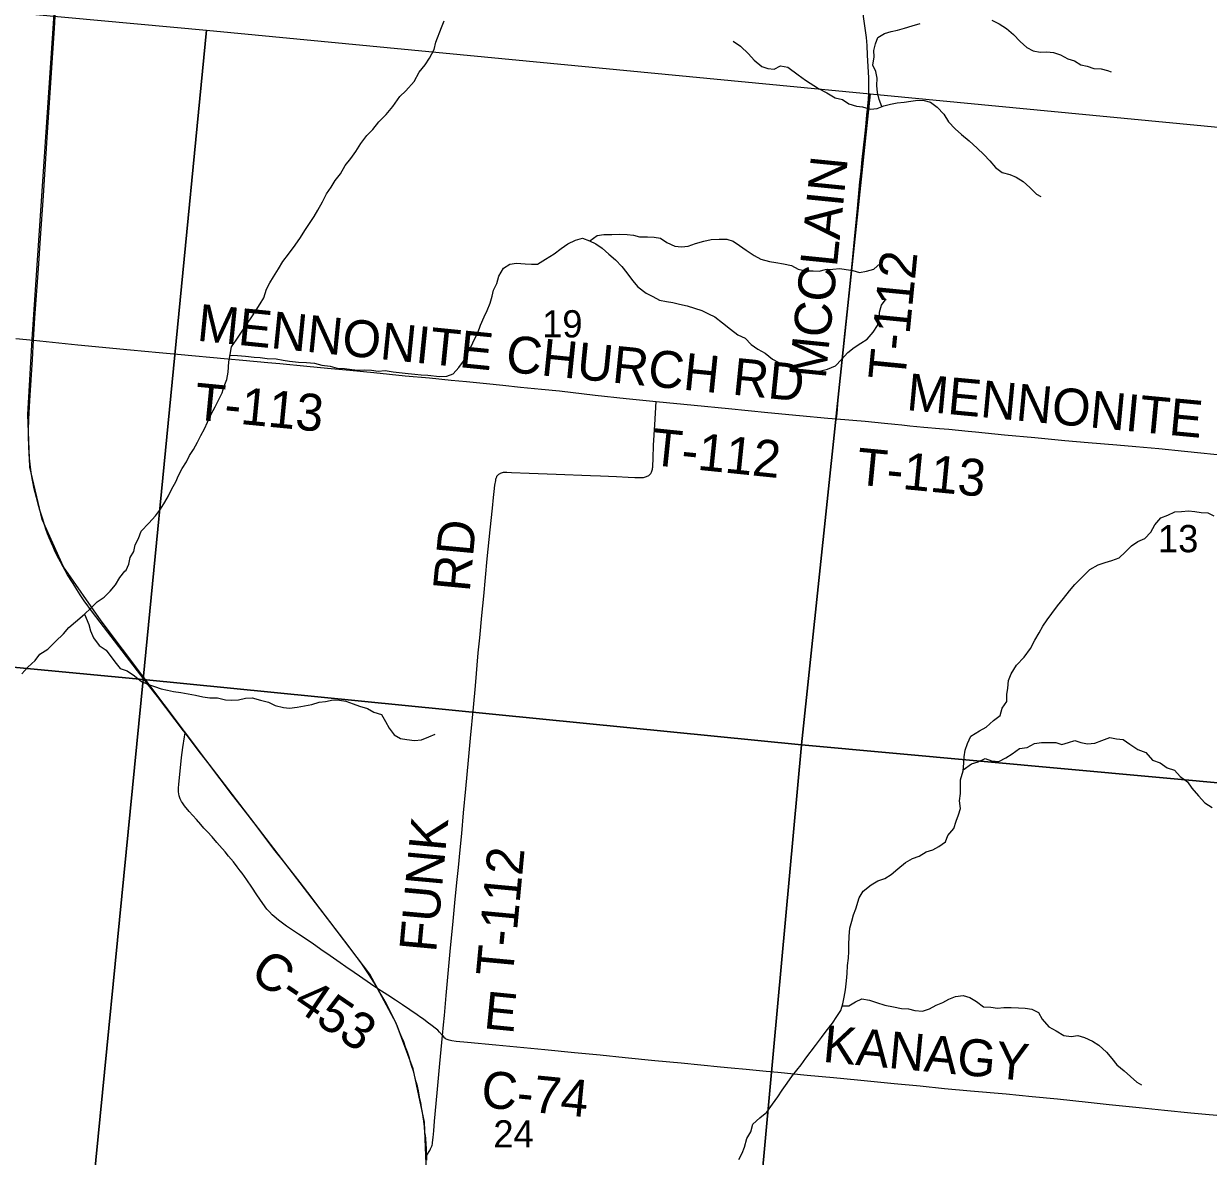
# Model space of a CAD drawing. Extents: x 831 to 1552, y 430 to 870.
# Drawn here: x 993.28 to 1029.71, y 742.52 to 777.36 of the extents above; entities that cross this region are included whole.
import ezdxf

# ---------------------------------------------------------------- set-up
doc = ezdxf.new("R2010")
doc.units = 0
for name, color, linetype in [('GM_X_Corporation', 7, 'Continuous'), ('GM_X_County_Road', 7, 'Continuous'), ('GM_X_County_Road_Text', 7, 'Continuous'), ('GM_X_Minor_River', 7, 'Continuous'), ('GM_X_Rail_Line', 7, 'Continuous'), ('GM_X_Section_Text', 7, 'Continuous'), ('GM_X_Township_Road', 7, 'Continuous'), ('GM_X_Township_Road_Text', 7, 'Continuous'), ('GM_X_US_Route', 7, 'Continuous')]:
    doc.layers.add(name, color=color, linetype=linetype)

msp = doc.modelspace()

# ---------------------------------------------------------------- linework, layer by layer
at = {"layer": 'GM_X_Corporation'}
for points in [[(998.895, 777.157), (996.953, 757.185), (977.893, 758.996), (979.447, 778.955)], [(1019.314, 775.201), (1017.196, 755.179), (996.953, 757.185), (998.895, 777.157)], [(1019.314, 775.201), (1040.822, 773.14), (1038.88, 753.198), (1017.196, 755.179)], [(996.953, 757.185), (994.975, 737.085), (974.695, 738.984), (977.893, 758.996)], [(1017.196, 755.179), (1015.357, 735.031), (994.975, 737.085), (996.953, 757.185)], [(1017.196, 755.179), (1038.88, 753.198), (1036.878, 732.803), (1015.357, 735.031)]]:
    msp.add_lwpolyline(points, close=True, dxfattribs=at)
at = {"layer": 'GM_X_County_Road'}
for points in [[(993.037, 767.675), (993.579, 767.622)], [(1004.165, 747.671), (1003.939, 747.827), (1003.602, 748.061), (1003.44, 748.175), (1003.185, 748.353), (1003.011, 748.473), (1002.706, 748.687), (1002.419, 748.884), (1002.144, 749.076), (1001.73, 749.351), (1001.361, 749.604), (1001.239, 749.69), (1001.109, 749.788), (1000.984, 749.892), (1000.919, 749.951), (1000.832, 750.041), (1000.758, 750.126), (1000.631, 750.296), (1000.446, 750.562), (1000.289, 750.801), (1000.135, 751.026), (999.993, 751.227), (999.937, 751.305), (999.847, 751.422), (999.725, 751.576), (999.576, 751.757), (999.474, 751.881), (999.3, 752.085), (999.219, 752.177), (999.071, 752.343), (998.93, 752.5), (998.821, 752.618), (998.722, 752.73), (998.59, 752.879), (998.366, 753.129), (998.222, 753.298), (998.199, 753.328), (998.156, 753.392), (998.132, 753.434), (998.108, 753.476), (998.093, 753.516), (998.079, 753.55), (998.063, 753.605), (998.05, 753.665), (998.041, 753.729), (998.038, 753.786), (998.039, 753.843), (998.046, 753.967), (998.074, 754.265), (998.134, 754.784), (998.172, 755.092), (998.223, 755.426), (998.241, 755.543)], [(1006.154, 746.232), (1006.062, 746.339), (1006.01, 746.395), (1005.934, 746.463), (1005.841, 746.537), (1005.69, 746.65), (1005.572, 746.736), (1005.492, 746.794), (1005.379, 746.871), (1004.932, 747.184), (1004.714, 747.328), (1004.472, 747.477), (1004.165, 747.671)], [(1005.671, 742.55), (1005.764, 742.701), (1005.791, 742.745), (1005.813, 742.786), (1005.83, 742.829), (1005.84, 742.867), (1005.847, 742.9), (1005.853, 742.946), (1005.869, 743.099), (1005.889, 743.306), (1005.915, 743.598), (1005.994, 744.47), (1006.079, 745.379), (1006.154, 746.232)], [(1006.154, 746.232), (1006.198, 746.187), (1006.239, 746.153), (1006.263, 746.138), (1006.292, 746.123), (1006.325, 746.111), (1006.356, 746.102), (1006.399, 746.093), (1006.443, 746.085), (1006.579, 746.066), (1006.926, 746.034), (1007.801, 745.952), (1009.302, 745.808), (1010.214, 745.715), (1011.009, 745.643), (1011.775, 745.563), (1012.69, 745.471), (1013.494, 745.391), (1014.707, 745.273), (1015.041, 745.24), (1015.498, 745.196), (1016.116, 745.141), (1016.475, 745.106), (1017.378, 745.019), (1018.182, 744.942), (1018.923, 744.87), (1020.055, 744.762), (1020.851, 744.683), (1021.602, 744.609), (1022.403, 744.538), (1023.491, 744.44), (1024.29, 744.364), (1025.076, 744.285), (1026.02, 744.186), (1026.664, 744.117), (1027.582, 744.025), (1028.364, 743.943), (1029.176, 743.858), (1030.422, 743.742)]]:
    msp.add_lwpolyline(points, dxfattribs=at)
at = {"layer": 'GM_X_Minor_River'}
for points in [[(996.427, 760.548), (996.514, 760.738), (996.554, 760.936), (996.663, 761.126), (996.702, 761.331), (996.803, 761.521), (996.889, 761.749), (997.12, 761.998), (997.335, 762.225), (997.481, 762.429), (997.62, 762.641), (997.729, 762.838), (997.829, 763.051), (997.953, 763.271), (998.039, 763.461), (998.155, 763.681), (998.286, 763.885), (998.379, 764.075), (998.503, 764.265), (998.627, 764.484), (998.72, 764.689), (998.836, 764.902), (998.929, 765.099), (999.045, 765.35), (999.169, 765.577), (999.263, 765.782), (999.379, 766.002), (999.442, 766.215), (999.527, 766.42), (999.567, 766.641), (999.585, 766.961), (999.625, 767.182), (999.665, 767.425), (999.812, 767.63), (999.974, 767.872), (1000.113, 768.077), (1000.275, 768.312), (1000.422, 768.547), (1000.545, 768.744), (1000.661, 768.933), (1000.74, 769.192), (1000.848, 769.389), (1000.964, 769.578), (1001.111, 769.821), (1001.25, 770.048), (1001.419, 770.276), (1001.627, 770.548), (1001.789, 770.783), (1001.921, 770.995), (1002.067, 771.215), (1002.206, 771.427), (1002.322, 771.624), (1002.469, 771.882), (1002.593, 772.125), (1002.732, 772.33), (1002.856, 772.534), (1003.018, 772.746), (1003.165, 772.997), (1003.334, 773.216), (1003.488, 773.428), (1003.65, 773.678), (1003.828, 773.921), (1004.02, 774.11), (1004.204, 774.344), (1004.427, 774.571), (1004.627, 774.813), (1004.843, 775.124), (1005.035, 775.297), (1005.282, 775.585), (1005.436, 775.865), (1005.621, 776.093), (1005.76, 776.297), (1005.9, 776.57), (1005.955, 776.791), (1006.126, 777.239), (1006.212, 777.452)], [(1019.667, 774.809), (1019.585, 775.034), (1019.541, 775.24), (1019.52, 775.461), (1019.53, 775.682), (1019.486, 775.889), (1019.396, 776.088), (1019.436, 776.339), (1019.423, 776.537), (1019.478, 776.743), (1019.548, 776.933), (1019.755, 777.06), (1019.954, 777.119), (1020.152, 777.163), (1020.373, 777.222), (1020.602, 777.296), (1020.847, 777.371)], [(1023.056, 777.465), (1023.276, 777.356), (1023.503, 777.209), (1023.722, 777.024), (1023.926, 776.816), (1024.13, 776.631), (1024.327, 776.523), (1024.54, 776.49), (1024.745, 776.496), (1024.951, 776.471), (1025.171, 776.401), (1025.391, 776.284), (1025.596, 776.214), (1025.793, 776.098), (1025.983, 776.058), (1026.195, 775.987), (1026.416, 775.97), (1026.613, 775.922), (1026.72, 775.883)], [(1015.1, 776.821), (1015.32, 776.674), (1015.569, 776.435), (1015.742, 776.236), (1015.977, 776.043), (1016.167, 775.98), (1016.364, 775.963), (1016.556, 776.06), (1016.784, 776.02), (1017.094, 775.789), (1017.328, 775.619), (1017.722, 775.371), (1017.98, 775.231), (1018.237, 775.077), (1018.458, 775.029), (1018.655, 774.897), (1018.89, 774.819), (1019.08, 774.802), (1019.323, 774.731), (1019.529, 774.752), (1019.728, 774.834), (1019.934, 774.886), (1020.14, 774.922), (1020.361, 774.943), (1020.559, 774.979), (1020.78, 775.008), (1020.97, 774.998), (1021.168, 774.951), (1021.372, 774.796), (1021.576, 774.581), (1021.726, 774.343), (1021.93, 774.128), (1022.126, 773.951), (1022.36, 773.758), (1022.602, 773.535), (1022.806, 773.342), (1022.995, 773.142), (1023.168, 772.942), (1023.372, 772.788), (1023.608, 772.717), (1023.805, 772.639), (1024.017, 772.508), (1024.228, 772.323), (1024.432, 772.115), (1024.561, 772.045)], [(999.622, 767.162), (999.853, 767.149), (1000.097, 767.131), (1000.363, 767.106), (1000.553, 767.089), (1000.766, 767.064), (1001.04, 767.047), (1001.261, 767.014), (1001.451, 766.982), (1001.725, 766.949), (1001.976, 766.939), (1002.22, 766.914), (1002.447, 766.858), (1002.706, 766.825), (1002.919, 766.762), (1003.139, 766.753), (1003.368, 766.72), (1003.558, 766.703), (1003.748, 766.709), (1003.969, 766.699), (1004.182, 766.667), (1004.395, 766.695), (1004.639, 766.655), (1004.913, 766.622), (1005.103, 766.605), (1005.308, 766.58), (1005.498, 766.563), (1005.704, 766.546), (1006.069, 766.505), (1006.29, 766.518), (1006.481, 766.585), (1006.665, 766.789), (1006.835, 767.024), (1006.913, 767.213), (1007.044, 767.433), (1007.145, 767.661), (1007.246, 767.851), (1007.324, 768.086), (1007.441, 768.345), (1007.534, 768.534), (1007.62, 768.762), (1007.682, 768.975), (1007.73, 769.165), (1007.831, 769.37), (1007.894, 769.598), (1008.033, 769.841), (1008.232, 769.961), (1008.438, 769.997), (1008.696, 769.972), (1008.894, 769.963), (1009.085, 769.961), (1009.33, 770.119), (1009.59, 770.284), (1009.805, 770.442), (1010.012, 770.593), (1010.249, 770.697), (1010.462, 770.764), (1010.683, 770.678), (1010.872, 770.593), (1011.069, 770.454), (1011.273, 770.276), (1011.477, 770.099), (1011.673, 769.891), (1011.831, 769.692), (1011.997, 769.462), (1012.17, 769.262), (1012.427, 769.069), (1012.632, 768.968), (1012.837, 768.859), (1013.049, 768.811), (1013.247, 768.787), (1013.452, 768.731), (1013.688, 768.684), (1013.908, 768.605), (1014.136, 768.542), (1014.34, 768.434), (1014.538, 768.34), (1014.772, 768.155), (1015.014, 767.962), (1015.241, 767.785), (1015.468, 767.684), (1015.649, 767.492), (1015.854, 767.345), (1016.081, 767.221), (1016.308, 767.043), (1016.505, 766.935), (1016.702, 766.849), (1016.937, 766.756), (1017.127, 766.693), (1017.386, 766.675), (1017.599, 766.658), (1017.79, 766.679), (1018.003, 766.731), (1018.248, 766.835), (1018.432, 767.032), (1018.625, 767.243), (1018.824, 767.402), (1019.023, 767.529), (1019.215, 767.657), (1019.407, 767.869), (1019.538, 768.081)], [(1010.685, 770.677), (1010.92, 770.844), (1011.118, 770.872), (1011.362, 770.878), (1011.591, 770.891), (1011.834, 770.881), (1012.032, 770.856), (1012.222, 770.809), (1012.466, 770.807), (1012.671, 770.797), (1012.861, 770.765), (1013.058, 770.633), (1013.301, 770.517), (1013.514, 770.492), (1013.712, 770.513), (1013.941, 770.595), (1014.201, 770.676), (1014.422, 770.72), (1014.666, 770.733), (1014.902, 770.731), (1015.099, 770.668), (1015.296, 770.537), (1015.5, 770.398), (1015.742, 770.228), (1015.947, 770.119), (1016.213, 770.048), (1016.411, 770.016), (1016.646, 769.975), (1016.889, 769.927), (1017.102, 769.811), (1017.322, 769.756), (1017.558, 769.761), (1017.748, 769.744), (1017.939, 769.796), (1018.168, 769.809), (1018.381, 769.83), (1018.579, 769.798), (1018.784, 769.773), (1018.982, 769.71), (1019.203, 769.746), (1019.424, 769.813), (1019.624, 769.986), (1019.616, 769.956)], [(1019.538, 768.081), (1019.586, 768.287), (1019.603, 768.485), (1019.658, 768.705), (1019.804, 768.902)], [(1018.652, 749.024), (1018.662, 749.283), (1018.687, 749.534), (1018.75, 749.755), (1018.797, 749.944), (1018.867, 750.134), (1018.97, 750.476), (1019.093, 750.68), (1019.346, 750.869), (1019.553, 750.989), (1019.767, 751.063), (1019.958, 751.191), (1020.165, 751.364), (1020.403, 751.56), (1020.61, 751.68), (1020.824, 751.754), (1021.038, 751.882), (1021.237, 751.948), (1021.428, 752.053), (1021.627, 752.196), (1021.705, 752.386), (1021.882, 752.605), (1021.953, 752.826), (1022.031, 753.023), (1022.093, 753.22), (1022.065, 753.457), (1022.09, 753.685), (1022.094, 754.104), (1022.172, 754.377), (1022.19, 754.613), (1022.199, 754.804), (1022.231, 755.009), (1022.302, 755.222), (1022.41, 755.449), (1022.678, 755.607), (1022.877, 755.72), (1023.108, 755.931), (1023.314, 756.081), (1023.37, 756.309), (1023.516, 756.506), (1023.511, 756.727), (1023.55, 756.925), (1023.568, 757.153), (1023.653, 757.366), (1023.816, 757.631), (1024.054, 757.873), (1024.247, 758.145), (1024.378, 758.396), (1024.51, 758.623), (1024.626, 758.828), (1024.757, 759.025), (1024.896, 759.222), (1025.073, 759.456), (1025.258, 759.683), (1025.443, 759.918), (1025.612, 760.114), (1026.073, 760.568), (1026.326, 760.71), (1026.539, 760.784), (1026.746, 760.851), (1026.967, 760.925), (1027.159, 761.106), (1027.351, 761.295), (1027.55, 761.431), (1027.757, 761.528), (1027.949, 761.724), (1028.073, 761.944), (1028.257, 762.156), (1028.471, 762.245), (1028.685, 762.343), (1028.884, 762.356), (1029.105, 762.377), (1029.295, 762.36), (1029.492, 762.32), (1029.698, 762.311), (1029.887, 762.225)], [(993.222, 757.362), (993.403, 757.569), (993.629, 757.768), (993.771, 757.962), (994.019, 758.122), (994.253, 758.351), (994.496, 758.595), (994.668, 758.788), (994.871, 758.965), (995.143, 759.193), (995.346, 759.384), (995.541, 759.577), (995.75, 759.715), (995.938, 759.907), (996.096, 760.101), (996.231, 760.325), (996.389, 760.518), (996.427, 760.548)], [(995.143, 759.193), (995.278, 758.876), (995.326, 758.685), (995.425, 758.468), (995.593, 758.235), (995.809, 758.092), (995.955, 757.897), (996.123, 757.679), (996.248, 757.523)], [(996.248, 757.523), (996.455, 757.454), (996.689, 757.299), (996.901, 757.13), (997.113, 757.029), (997.303, 756.974), (997.508, 756.895), (997.698, 756.856), (997.888, 756.823), (998.109, 756.783), (998.337, 756.743), (998.565, 756.71), (998.785, 756.655), (999.006, 756.623), (999.234, 756.62), (999.485, 756.557), (999.675, 756.548), (999.881, 756.561), (1000.095, 756.612), (1000.3, 756.626), (1000.559, 756.555), (1000.809, 756.492), (1001.014, 756.383), (1001.265, 756.327), (1001.455, 756.31), (1001.684, 756.339), (1001.912, 756.375), (1002.141, 756.418), (1002.363, 756.493), (1002.561, 756.506), (1002.797, 756.557), (1002.988, 756.548), (1003.185, 756.523), (1003.413, 756.437), (1003.603, 756.367), (1003.846, 756.296), (1004.05, 756.187), (1004.278, 756.109), (1004.406, 755.895), (1004.518, 755.695), (1004.669, 755.488), (1004.866, 755.372), (1005.063, 755.34), (1005.299, 755.315), (1005.512, 755.328), (1005.742, 755.425), (1005.933, 755.507)], [(1022.175, 754.411), (1022.433, 754.596), (1022.639, 754.655), (1022.853, 754.76), (1023.043, 754.69), (1023.271, 754.665), (1023.486, 754.777), (1023.677, 754.905), (1023.907, 755.063), (1024.143, 755.099), (1024.365, 755.219), (1024.586, 755.247), (1024.792, 755.253), (1025.02, 755.251), (1025.21, 755.188), (1025.416, 755.247), (1025.607, 755.307), (1025.797, 755.252), (1025.995, 755.212), (1026.223, 755.233), (1026.437, 755.315), (1026.682, 755.404), (1026.894, 755.364), (1027.092, 755.339), (1027.304, 755.2), (1027.546, 755.038), (1027.789, 754.937), (1027.993, 754.707), (1028.235, 754.621), (1028.447, 754.467), (1028.668, 754.396), (1028.848, 754.204), (1029.075, 754.042), (1029.211, 753.843), (1029.407, 753.605), (1029.61, 753.39), (1029.83, 753.251)], [(1015.272, 742.426), (1015.373, 742.616), (1015.443, 742.805), (1015.522, 743.071), (1015.638, 743.275), (1015.708, 743.51), (1015.916, 743.706), (1016.131, 743.879), (1016.308, 744.121), (1016.47, 744.348), (1016.601, 744.552), (1016.763, 744.771), (1016.925, 745.006), (1017.195, 745.331), (1017.333, 745.535), (1017.626, 745.928), (1017.811, 746.17), (1017.958, 746.374), (1018.158, 746.616), (1018.289, 746.82), (1018.405, 747.009), (1018.468, 747.207), (1018.516, 747.419), (1018.556, 747.64), (1018.581, 747.921), (1018.606, 748.142), (1018.616, 748.385), (1018.641, 748.613), (1018.658, 748.819), (1018.652, 749.024)], [(1018.45, 747.151), (1018.658, 747.144), (1018.864, 747.272), (1019.056, 747.369), (1019.291, 747.321), (1019.511, 747.251), (1019.762, 747.172), (1020.028, 747.117), (1020.279, 747.069), (1020.492, 747.052), (1020.69, 747.004), (1020.925, 746.987), (1021.139, 747.054), (1021.338, 747.166), (1021.545, 747.248), (1021.736, 747.353), (1021.942, 747.435), (1022.171, 747.463), (1022.376, 747.408), (1022.588, 747.277), (1022.8, 747.115), (1023.02, 747.106), (1023.226, 747.081), (1023.424, 747.102), (1023.645, 747.093), (1023.873, 747.09), (1024.079, 747.073), (1024.284, 747.041), (1024.488, 746.94), (1024.601, 746.734), (1024.812, 746.504), (1025.032, 746.38), (1025.274, 746.233), (1025.495, 746.209), (1025.7, 746.237), (1025.905, 746.175), (1026.148, 746.066), (1026.345, 745.943), (1026.579, 745.728), (1026.745, 745.528), (1026.895, 745.329), (1027.122, 745.152), (1027.515, 744.799), (1027.659, 744.714)]]:
    msp.add_lwpolyline(points, dxfattribs=at)
at = {"layer": 'GM_X_Rail_Line'}
msp.add_lwpolyline([(997.388, 650.938), (997.987, 656.381), (998.443, 662.173), (999.567, 676.345), (1001.482, 696.666), (1003.414, 714.776), (1003.551, 716.542), (1004.517, 727.567), (1005.667, 742.027), (1005.605, 743.565), (1005.257, 745.206), (1004.732, 746.62), (1003.92, 748.118), (1002.725, 749.701), (998.874, 754.713), (995.664, 758.989), (994.502, 760.652), (993.842, 762.104), (993.466, 763.719), (993.405, 765.341), (993.538, 767.661), (994.84, 786.938)], dxfattribs=at)
at = {"layer": 'GM_X_Township_Road'}
for points in [[(1018.279, 765.205), (1018.294, 765.374), (1018.343, 765.919), (1018.379, 766.297), (1018.465, 767.119), (1018.538, 767.833), (1018.605, 768.5), (1018.686, 769.279), (1018.744, 769.872), (1018.853, 770.947), (1018.892, 771.355), (1018.922, 771.677), (1018.976, 772.257), (1018.999, 772.492), (1019.014, 772.653), (1019.031, 772.826), (1019.067, 773.183), (1019.145, 773.906), (1019.176, 774.192), (1019.211, 774.557), (1019.237, 774.823), (1019.257, 775.04), (1019.267, 775.211), (1019.274, 775.431), (1019.267, 775.698), (1019.234, 776.397), (1019.218, 776.694), (1019.198, 776.937), (1019.181, 777.079), (1019.162, 777.22), (1019.06, 777.947)], [(993.579, 767.622), (994.941, 767.485), (996.562, 767.333), (997.44, 767.25), (998.009, 767.197), (999.556, 767.054), (1000.014, 767.011), (1000.781, 766.939), (1001.152, 766.903), (1001.98, 766.825), (1002.624, 766.765), (1003.304, 766.7), (1004.046, 766.626), (1005.01, 766.532), (1005.753, 766.462), (1006.42, 766.397), (1006.891, 766.352), (1007.509, 766.293), (1008.016, 766.241), (1008.559, 766.182), (1009.201, 766.121), (1009.756, 766.065), (1010.854, 765.933), (1011.803, 765.829), (1012.732, 765.74)], [(1011.873, 763.414), (1012.077, 763.405), (1012.264, 763.4), (1012.304, 763.402), (1012.338, 763.405), (1012.373, 763.41), (1012.399, 763.417), (1012.432, 763.427), (1012.458, 763.438), (1012.481, 763.451), (1012.5, 763.463), (1012.529, 763.486), (1012.548, 763.507), (1012.561, 763.524), (1012.575, 763.545), (1012.587, 763.567), (1012.598, 763.594), (1012.608, 763.625), (1012.616, 763.659), (1012.621, 763.687), (1012.624, 763.718), (1012.627, 763.747), (1012.635, 763.982), (1012.652, 764.392), (1012.688, 765.025), (1012.732, 765.74)], [(1012.732, 765.74), (1013.895, 765.623), (1014.951, 765.521), (1016.161, 765.403), (1017.138, 765.307), (1018.009, 765.228), (1018.279, 765.205)], [(1018.279, 765.205), (1019.163, 765.13), (1019.755, 765.073), (1020.076, 765.04), (1020.286, 765.018), (1020.534, 764.994), (1020.967, 764.954), (1021.449, 764.908), (1021.734, 764.885), (1022.328, 764.831), (1022.553, 764.807), (1023.44, 764.716), (1024.375, 764.627), (1025.305, 764.544), (1026.015, 764.482), (1026.9, 764.403), (1027.485, 764.35), (1028.192, 764.288), (1028.981, 764.206), (1030.385, 764.064)], [(1006.154, 746.232), (1006.189, 746.564), (1006.219, 746.853), (1006.275, 747.465), (1006.347, 748.251), (1006.406, 748.928), (1006.475, 749.641), (1006.54, 750.314), (1006.6, 750.944), (1006.646, 751.402), (1006.699, 751.946), (1006.748, 752.452), (1006.805, 753.083), (1006.871, 753.826), (1006.955, 754.705), (1007.018, 755.383), (1007.107, 756.33), (1007.169, 756.997), (1007.26, 758.008), (1007.306, 758.466), (1007.372, 759.158), (1007.425, 759.746), (1007.534, 760.903), (1007.626, 761.788), (1007.692, 762.46), (1007.724, 762.781), (1007.745, 762.966), (1007.772, 763.164), (1007.794, 763.31), (1007.802, 763.346), (1007.809, 763.379), (1007.818, 763.406), (1007.825, 763.424), (1007.834, 763.44), (1007.844, 763.456), (1007.856, 763.47), (1007.867, 763.482), (1007.882, 763.497), (1007.895, 763.507), (1007.908, 763.516), (1007.927, 763.528), (1007.946, 763.537), (1007.975, 763.549), (1008.002, 763.556), (1008.031, 763.561), (1008.059, 763.563), (1008.097, 763.563), (1008.141, 763.563), (1008.278, 763.558), (1008.824, 763.536), (1009.656, 763.501), (1010.712, 763.461), (1011.022, 763.451), (1011.506, 763.431), (1011.873, 763.414)]]:
    msp.add_lwpolyline(points, dxfattribs=at)
at = {"layer": 'GM_X_US_Route'}
msp.add_lwpolyline([(1005.675, 742.4), (1005.671, 742.55), (1005.67, 742.604), (1005.665, 742.762), (1005.655, 742.903), (1005.641, 743.069), (1005.631, 743.161), (1005.619, 743.257), (1005.603, 743.424), (1005.581, 743.597), (1005.562, 743.729), (1005.542, 743.865), (1005.516, 744.025), (1005.488, 744.171), (1005.455, 744.344), (1005.419, 744.529), (1005.384, 744.674), (1005.349, 744.81), (1005.307, 744.976), (1005.262, 745.134), (1005.218, 745.286), (1005.178, 745.417), (1005.133, 745.565), (1005.08, 745.72), (1005.024, 745.879), (1004.965, 746.04), (1004.911, 746.177), (1004.85, 746.323), (1004.769, 746.514), (1004.69, 746.693), (1004.621, 746.833), (1004.555, 746.963), (1004.495, 747.089), (1004.434, 747.206), (1004.353, 747.354), (1004.291, 747.461), (1004.204, 747.605), (1004.165, 747.671), (1004.113, 747.761), (1003.972, 747.992), (1003.883, 748.135), (1003.776, 748.291), (1003.673, 748.441), (1003.559, 748.598), (1003.29, 748.962), (1002.398, 750.135), (1002.121, 750.505), (1001.785, 750.941), (1001.305, 751.546), (1000.971, 751.973), (1000.424, 752.692), (1000.033, 753.2), (999.701, 753.631), (998.936, 754.632), (998.645, 755.017), (998.241, 755.543), (998.188, 755.612), (997.387, 756.662), (997.114, 757.017), (995.964, 758.514), (995.397, 759.263), (995.138, 759.612), (995.017, 759.789), (994.915, 759.952), (994.846, 760.059), (994.775, 760.171), (994.625, 760.409), (994.551, 760.541), (994.492, 760.652), (994.407, 760.81), (994.32, 760.975), (994.228, 761.164), (994.178, 761.272), (994.129, 761.382), (994.063, 761.54), (994.012, 761.668), (993.961, 761.811), (993.863, 762.116), (993.777, 762.392), (993.713, 762.617), (993.669, 762.788), (993.598, 763.053), (993.547, 763.319), (993.509, 763.551), (993.478, 763.812), (993.448, 764.095), (993.43, 764.389), (993.422, 764.629), (993.419, 764.851), (993.43, 765.198), (993.466, 765.77), (993.542, 767.033), (993.579, 767.622), (993.623, 768.31), (993.731, 769.833), (993.795, 770.767), (993.881, 772.079), (993.925, 772.718), (994.007, 774.012), (994.224, 777.228), (994.258, 777.759)], dxfattribs=at)

# ---------------------------------------------------------------- texts
at = {"layer": 'GM_X_County_Road_Text'}
for s, height, rotation, p in [('C-453', 1.1364, 325.7039, (1000.184, 748.025)), ('E', 1.136, 354.2881, (1007.399, 746.462)), ('KANAGY', 1.1364, 354.6107, (1017.831, 745.429)), ('C-74', 1.1364, 354.4949, (1007.315, 744.035))]:
    msp.add_text(s, height=height, rotation=rotation, dxfattribs=at).set_placement(p)
at = {"layer": 'GM_X_Section_Text'}
for s, p in [('19', (1009.221, 767.71)), ('13', (1028.163, 761.102)), ('24', (1007.721, 742.791))]:
    msp.add_text(s, height=0.8371, rotation=0, dxfattribs=at).set_placement(p)
at = {"layer": 'GM_X_Township_Road_Text'}
for s, height, rotation, p in [('MCCLAIN', 1.1364, 84.2596, (1017.943, 766.412)), ('T-112', 1.1364, 84.4016, (1020.384, 766.359)), ('MENNONITE CHURCH RD', 1.13636, 354.2496, (998.583, 767.612)), ('T-113', 1.1364, 354.456, (998.49, 765.188)), ('MENNONITE', 1.1364, 354.5985, (1020.407, 765.478)), ('T-112', 1.1364, 354.1221, (1012.547, 763.789)), ('T-113', 1.1364, 354.4553, (1018.857, 763.188)), ('RD', 1.1364, 84.5841, (1006.992, 759.859)), ('FUNK', 1.1364, 84.7145, (1005.959, 748.773)), ('T-112', 1.1364, 84.6795, (1008.318, 748.021))]:
    msp.add_text(s, height=height, rotation=rotation, dxfattribs=at).set_placement(p)

doc.saveas('drawing.dxf')
